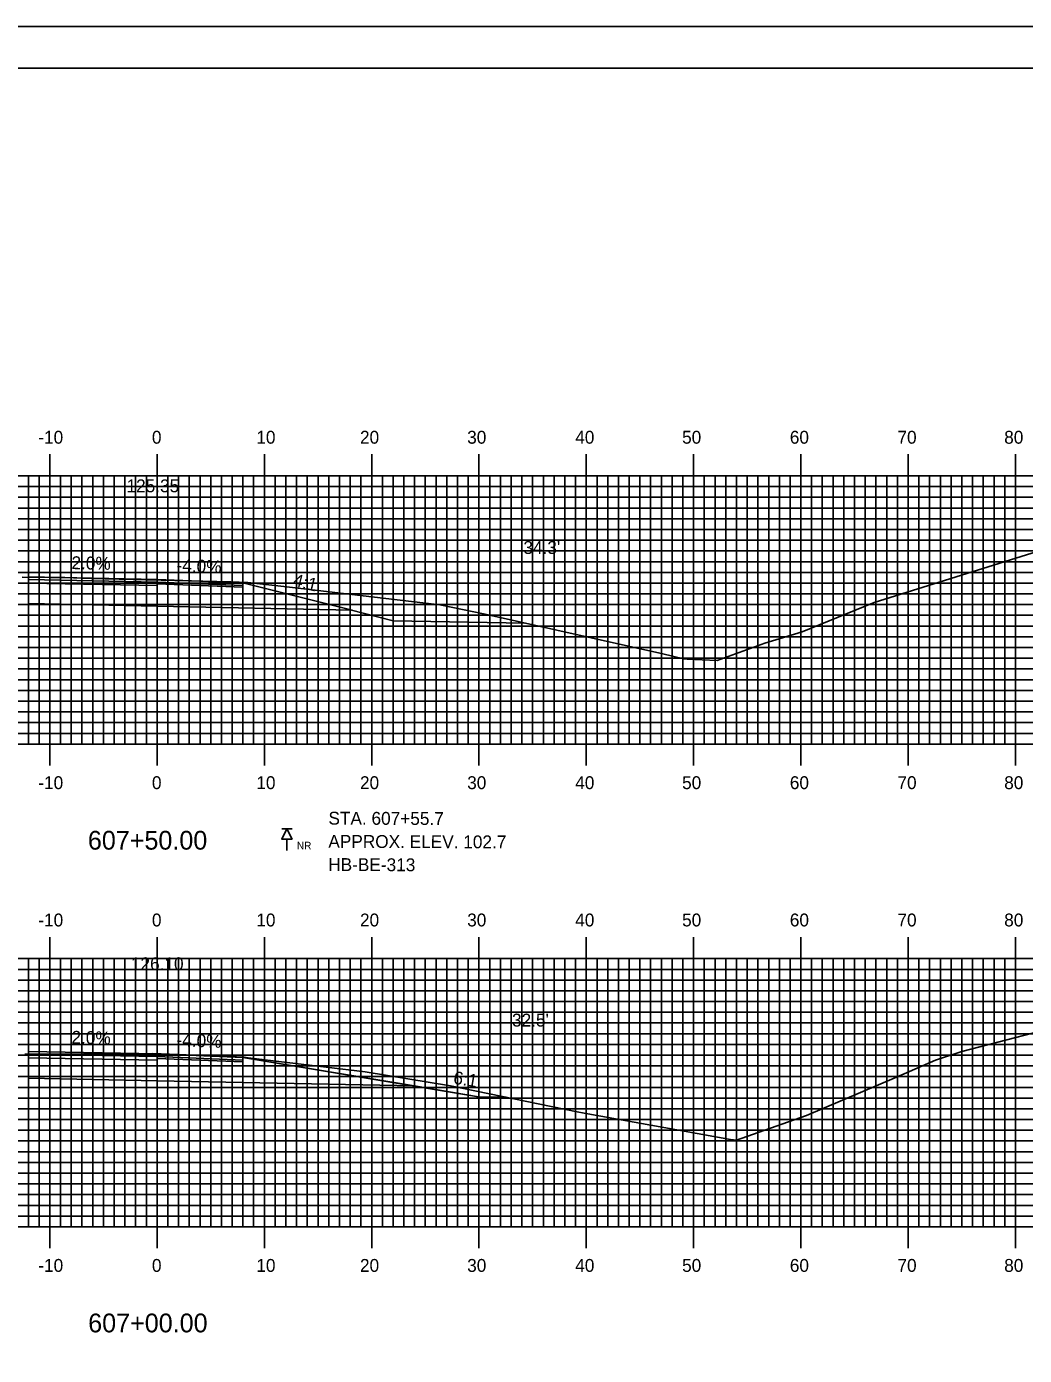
# Model space of a CAD drawing. Extents: x 842569 to 842912, y 363538 to 363758.
# Drawn here: x 842722.2 to 842815.2, y 363633.7 to 363757.6 of the extents above; entities that cross this region are included whole.
import ezdxf

# ---------------------------------------------------------------- set-up
doc = ezdxf.new("R2010")
doc.units = 0
for name, color, linetype in [('ANNOTATION', 7, 'Continuous'), ('BORDER', 7, 'Continuous'), ('BORING - NO REFUSAL', 7, 'Continuous'), ('D_Roadway_Centerline', 7, 'Continuous'), ('D_Roadway_Centerline_Text', 7, 'Continuous'), ('D_Roadway_Edge_Shoulder', 7, 'Continuous'), ('D_Roadway_Edge_TW', 7, 'Continuous'), ('D_Roadway_FinishedGrade', 7, 'Continuous'), ('D_Roadway_Pavement', 7, 'Continuous'), ('D_Roadway_SlopeLines', 7, 'Continuous'), ('D_Roadway_SubGrade', 7, 'Continuous'), ('D_Text_Standard', 7, 'Continuous'), ('H_V ANNOTATION', 7, 'Continuous'), ('MAJOR', 7, 'Continuous'), ('MINOR', 7, 'Continuous'), ('PLOT BOUNDARY', 7, 'Continuous'), ('S_Roadway_Centerline', 7, 'Continuous')]:
    doc.layers.add(name, color=color, linetype=linetype)

msp = doc.modelspace()

# ---------------------------------------------------------------- linework, layer by layer
at = {"layer": 'BORDER'}
msp.add_lwpolyline([(842584.8, 363543.72), (842904.8, 363543.72), (842904.8, 363753.72), (842584.8, 363753.72)], close=True, dxfattribs=at)
at = {"layer": 'BORING - NO REFUSAL'}
for p, q in [((842746.98, 363682.82), (842746.02, 363682.82)), ((842746.5, 363681.86), (842746.5, 363680.8))]:
    msp.add_line(p, q, dxfattribs=at)
msp.add_lwpolyline([(842746.5, 363682.82), (842746.98, 363681.86), (842746.02, 363681.86)], close=True, dxfattribs=at)
at = {"layer": 'D_Roadway_Centerline'}
for points in [[(842722.4, 363706.31), (842734.4, 363706.07), (842742.4, 363705.75), (842752.57, 363703.21)], [(842722.4, 363662.07), (842734.4, 363661.83), (842742.4, 363661.51), (842758.35, 363658.85), (842764.35, 363657.85)]]:
    msp.add_lwpolyline(points, dxfattribs=at)
at = {"layer": 'D_Roadway_Edge_Shoulder'}
msp.add_line((842722.4, 363706.06), (842722.4, 363706.31), dxfattribs=at)
for points in [[(842734.4, 363706.07), (842742.4, 363705.75), (842742.4, 363705.5), (842734.4, 363705.82)], [(842734.4, 363661.83), (842742.4, 363661.51), (842742.4, 363661.26), (842734.4, 363661.58)]]:
    msp.add_lwpolyline(points, close=True, dxfattribs=at)
at = {"layer": 'D_Roadway_Edge_TW'}
for points in [[(842722.4, 363706.31), (842734.4, 363706.07), (842734.4, 363705.82), (842722.4, 363706.06)], [(842722.4, 363662.07), (842734.4, 363661.83), (842734.4, 363661.58), (842722.4, 363661.82)]]:
    msp.add_lwpolyline(points, close=True, dxfattribs=at)
msp.add_lwpolyline([(842722.4, 363662.07), (842722.4, 363661.82)], dxfattribs=at)
at = {"layer": 'D_Roadway_FinishedGrade'}
for points in [[(842752.4, 363703.22), (842756.4, 363702.22), (842768.66, 363701.98)], [(842758.35, 363658.85), (842764.35, 363657.85), (842766.94, 363657.79)]]:
    msp.add_lwpolyline(points, dxfattribs=at)
at = {"layer": 'D_Roadway_Pavement'}
msp.add_line((842722.4, 363705.73), (842722.4, 363706.06), dxfattribs=at)
for points in [[(842722.4, 363706.06), (842734.4, 363705.82), (842734.4, 363705.49), (842722.4, 363705.73)], [(842734.4, 363705.82), (842742.4, 363705.5), (842742.4, 363705.34), (842734.4, 363705.66)], [(842722.4, 363661.82), (842734.4, 363661.58), (842734.4, 363661.24), (842722.4, 363661.48)], [(842734.4, 363661.58), (842742.4, 363661.26), (842742.4, 363661.09), (842734.4, 363661.41)]]:
    msp.add_lwpolyline(points, close=True, dxfattribs=at)
for points in [[(842734.4, 363705.82), (842734.4, 363705.49)], [(842734.4, 363705.82), (842734.4, 363705.49)], [(842722.4, 363661.82), (842722.4, 363661.48)], [(842734.4, 363661.58), (842734.4, 363661.24)], [(842734.4, 363661.58), (842734.4, 363661.24)]]:
    msp.add_lwpolyline(points, dxfattribs=at)
at = {"layer": 'D_Roadway_SlopeLines'}
msp.add_lwpolyline([(842742.4, 363661.51), (842764.35, 363657.85)], dxfattribs=at)
at = {"layer": 'D_Roadway_SubGrade'}
for p, q in [((842722.4, 363714.91), (842722.4, 363703.81)), ((842722.4, 363703.81), (842722.4, 363705.73)), ((842722.4, 363670.66), (842722.4, 363659.57))]:
    msp.add_line(p, q, dxfattribs=at)
for points in [[(842722.4, 363705.73), (842734.4, 363705.49), (842734.4, 363703.57), (842722.4, 363703.81)], [(842734.4, 363705.49), (842734.4, 363705.82), (842742.4, 363705.5), (842742.4, 363705.75), (842752.57, 363703.21), (842734.4, 363703.57)], [(842722.4, 363661.48), (842734.4, 363661.24), (842734.4, 363659.33), (842722.4, 363659.57)], [(842734.4, 363661.24), (842734.4, 363661.58), (842742.4, 363661.26), (842742.4, 363661.51), (842758.35, 363658.85), (842734.4, 363659.33)]]:
    msp.add_lwpolyline(points, close=True, dxfattribs=at)
msp.add_lwpolyline([(842722.4, 363661.48), (842722.4, 363659.57)], dxfattribs=at)
at = {"layer": 'MAJOR'}
for p, q in [((842724.4, 363717.73), (842724.4, 363715.72)), ((842734.4, 363717.73), (842734.4, 363715.72)), ((842744.4, 363717.73), (842744.4, 363715.72)), ((842754.4, 363717.73), (842754.4, 363715.72)), ((842764.4, 363717.73), (842764.4, 363715.72)), ((842774.4, 363717.73), (842774.4, 363715.72)), ((842784.4, 363717.73), (842784.4, 363715.72)), ((842794.4, 363717.73), (842794.4, 363715.72)), ((842804.4, 363717.73), (842804.4, 363715.72)), ((842814.4, 363717.73), (842814.4, 363715.72)), ((842594.4, 363715.72), (842874.4, 363715.72)), ((842594.4, 363715.72), (842874.4, 363715.72)), ((842724.4, 363690.72), (842724.4, 363715.72)), ((842734.4, 363690.72), (842734.4, 363715.72)), ((842744.4, 363690.72), (842744.4, 363715.72)), ((842754.4, 363690.72), (842754.4, 363715.72)), ((842764.4, 363690.72), (842764.4, 363715.72)), ((842774.4, 363690.72), (842774.4, 363715.72)), ((842784.4, 363690.72), (842784.4, 363715.72)), ((842794.4, 363690.72), (842794.4, 363715.72)), ((842804.4, 363690.72), (842804.4, 363715.72)), ((842814.4, 363690.72), (842814.4, 363715.72)), ((842594.4, 363710.72), (842874.4, 363710.72)), ((842594.4, 363705.72), (842874.4, 363705.72)), ((842594.4, 363700.72), (842874.4, 363700.72)), ((842594.4, 363695.72), (842874.4, 363695.72)), ((842594.4, 363690.72), (842874.4, 363690.72)), ((842594.4, 363690.72), (842874.4, 363690.72)), ((842724.4, 363688.72), (842724.4, 363690.72)), ((842734.4, 363688.72), (842734.4, 363690.72)), ((842744.4, 363688.72), (842744.4, 363690.72)), ((842754.4, 363688.72), (842754.4, 363690.72)), ((842764.4, 363688.72), (842764.4, 363690.72)), ((842774.4, 363688.72), (842774.4, 363690.72)), ((842784.4, 363688.72), (842784.4, 363690.72)), ((842794.4, 363688.72), (842794.4, 363690.72)), ((842804.4, 363688.72), (842804.4, 363690.72)), ((842814.4, 363688.72), (842814.4, 363690.72)), ((842724.4, 363672.73), (842724.4, 363670.72)), ((842734.4, 363672.73), (842734.4, 363670.72)), ((842744.4, 363672.73), (842744.4, 363670.72)), ((842754.4, 363672.73), (842754.4, 363670.72)), ((842764.4, 363672.73), (842764.4, 363670.72)), ((842774.4, 363672.73), (842774.4, 363670.72)), ((842784.4, 363672.73), (842784.4, 363670.72)), ((842794.4, 363672.73), (842794.4, 363670.72)), ((842804.4, 363672.73), (842804.4, 363670.72)), ((842814.4, 363672.73), (842814.4, 363670.72)), ((842594.4, 363670.72), (842874.4, 363670.72)), ((842594.4, 363670.72), (842874.4, 363670.72)), ((842724.4, 363645.72), (842724.4, 363670.72)), ((842734.4, 363645.72), (842734.4, 363670.72)), ((842744.4, 363645.72), (842744.4, 363670.72)), ((842754.4, 363645.72), (842754.4, 363670.72)), ((842764.4, 363645.72), (842764.4, 363670.72)), ((842774.4, 363645.72), (842774.4, 363670.72)), ((842784.4, 363645.72), (842784.4, 363670.72)), ((842794.4, 363645.72), (842794.4, 363670.72)), ((842804.4, 363645.72), (842804.4, 363670.72)), ((842814.4, 363645.72), (842814.4, 363670.72)), ((842594.4, 363665.72), (842874.4, 363665.72)), ((842594.4, 363660.72), (842874.4, 363660.72)), ((842594.4, 363655.72), (842874.4, 363655.72)), ((842594.4, 363650.72), (842874.4, 363650.72)), ((842594.4, 363645.72), (842874.4, 363645.72)), ((842594.4, 363645.72), (842874.4, 363645.72)), ((842724.4, 363643.72), (842724.4, 363645.72)), ((842734.4, 363643.72), (842734.4, 363645.72)), ((842744.4, 363643.72), (842744.4, 363645.72)), ((842754.4, 363643.72), (842754.4, 363645.72)), ((842764.4, 363643.72), (842764.4, 363645.72)), ((842774.4, 363643.72), (842774.4, 363645.72)), ((842784.4, 363643.72), (842784.4, 363645.72)), ((842794.4, 363643.72), (842794.4, 363645.72)), ((842804.4, 363643.72), (842804.4, 363645.72)), ((842814.4, 363643.72), (842814.4, 363645.72))]:
    msp.add_line(p, q, dxfattribs=at)
at = {"layer": 'MINOR'}
for p, q in [((842722.4, 363690.72), (842722.4, 363715.72)), ((842723.4, 363690.72), (842723.4, 363715.72)), ((842725.4, 363690.72), (842725.4, 363715.72)), ((842726.4, 363690.72), (842726.4, 363715.72)), ((842727.4, 363690.72), (842727.4, 363715.72)), ((842728.4, 363690.72), (842728.4, 363715.72)), ((842729.4, 363690.72), (842729.4, 363715.72)), ((842730.4, 363690.72), (842730.4, 363715.72)), ((842731.4, 363690.72), (842731.4, 363715.72)), ((842732.4, 363690.72), (842732.4, 363715.72)), ((842733.4, 363690.72), (842733.4, 363715.72)), ((842735.4, 363690.72), (842735.4, 363715.72)), ((842736.4, 363690.72), (842736.4, 363715.72)), ((842737.4, 363690.72), (842737.4, 363715.72)), ((842738.4, 363690.72), (842738.4, 363715.72)), ((842739.4, 363690.72), (842739.4, 363715.72)), ((842740.4, 363690.72), (842740.4, 363715.72)), ((842741.4, 363690.72), (842741.4, 363715.72)), ((842742.4, 363690.72), (842742.4, 363715.72)), ((842743.4, 363690.72), (842743.4, 363715.72)), ((842745.4, 363690.72), (842745.4, 363715.72)), ((842746.4, 363690.72), (842746.4, 363715.72)), ((842747.4, 363690.72), (842747.4, 363715.72)), ((842748.4, 363690.72), (842748.4, 363715.72)), ((842749.4, 363690.72), (842749.4, 363715.72)), ((842750.4, 363690.72), (842750.4, 363715.72)), ((842751.4, 363690.72), (842751.4, 363715.72)), ((842752.4, 363690.72), (842752.4, 363715.72)), ((842753.4, 363690.72), (842753.4, 363715.72)), ((842755.4, 363690.72), (842755.4, 363715.72)), ((842756.4, 363690.72), (842756.4, 363715.72)), ((842757.4, 363690.72), (842757.4, 363715.72)), ((842758.4, 363690.72), (842758.4, 363715.72)), ((842759.4, 363690.72), (842759.4, 363715.72)), ((842760.4, 363690.72), (842760.4, 363715.72)), ((842761.4, 363690.72), (842761.4, 363715.72)), ((842762.4, 363690.72), (842762.4, 363715.72)), ((842763.4, 363690.72), (842763.4, 363715.72)), ((842765.4, 363690.72), (842765.4, 363715.72)), ((842766.4, 363690.72), (842766.4, 363715.72)), ((842767.4, 363690.72), (842767.4, 363715.72)), ((842768.4, 363690.72), (842768.4, 363715.72)), ((842769.4, 363690.72), (842769.4, 363715.72)), ((842770.4, 363690.72), (842770.4, 363715.72)), ((842771.4, 363690.72), (842771.4, 363715.72)), ((842772.4, 363690.72), (842772.4, 363715.72)), ((842773.4, 363690.72), (842773.4, 363715.72)), ((842775.4, 363690.72), (842775.4, 363715.72)), ((842776.4, 363690.72), (842776.4, 363715.72)), ((842777.4, 363690.72), (842777.4, 363715.72)), ((842778.4, 363690.72), (842778.4, 363715.72)), ((842779.4, 363690.72), (842779.4, 363715.72)), ((842780.4, 363690.72), (842780.4, 363715.72)), ((842781.4, 363690.72), (842781.4, 363715.72)), ((842782.4, 363690.72), (842782.4, 363715.72)), ((842783.4, 363690.72), (842783.4, 363715.72)), ((842785.4, 363690.72), (842785.4, 363715.72)), ((842786.4, 363690.72), (842786.4, 363715.72)), ((842787.4, 363690.72), (842787.4, 363715.72)), ((842788.4, 363690.72), (842788.4, 363715.72)), ((842789.4, 363690.72), (842789.4, 363715.72)), ((842790.4, 363690.72), (842790.4, 363715.72)), ((842791.4, 363690.72), (842791.4, 363715.72)), ((842792.4, 363690.72), (842792.4, 363715.72)), ((842793.4, 363690.72), (842793.4, 363715.72)), ((842795.4, 363690.72), (842795.4, 363715.72)), ((842796.4, 363690.72), (842796.4, 363715.72)), ((842797.4, 363690.72), (842797.4, 363715.72)), ((842798.4, 363690.72), (842798.4, 363715.72)), ((842799.4, 363690.72), (842799.4, 363715.72)), ((842800.4, 363690.72), (842800.4, 363715.72)), ((842801.4, 363690.72), (842801.4, 363715.72)), ((842802.4, 363690.72), (842802.4, 363715.72)), ((842803.4, 363690.72), (842803.4, 363715.72)), ((842805.4, 363690.72), (842805.4, 363715.72)), ((842806.4, 363690.72), (842806.4, 363715.72)), ((842807.4, 363690.72), (842807.4, 363715.72)), ((842808.4, 363690.72), (842808.4, 363715.72)), ((842809.4, 363690.72), (842809.4, 363715.72)), ((842810.4, 363690.72), (842810.4, 363715.72)), ((842811.4, 363690.72), (842811.4, 363715.72)), ((842812.4, 363690.72), (842812.4, 363715.72)), ((842813.4, 363690.72), (842813.4, 363715.72)), ((842594.4, 363714.72), (842874.4, 363714.72)), ((842594.4, 363713.72), (842874.4, 363713.72)), ((842594.4, 363712.72), (842874.4, 363712.72)), ((842594.4, 363711.72), (842874.4, 363711.72)), ((842594.4, 363709.72), (842874.4, 363709.72)), ((842594.4, 363708.72), (842874.4, 363708.72)), ((842594.4, 363707.72), (842874.4, 363707.72)), ((842594.4, 363706.72), (842874.4, 363706.72)), ((842594.4, 363704.72), (842874.4, 363704.72)), ((842594.4, 363703.72), (842874.4, 363703.72)), ((842594.4, 363702.72), (842874.4, 363702.72)), ((842594.4, 363701.72), (842874.4, 363701.72)), ((842594.4, 363699.72), (842874.4, 363699.72)), ((842594.4, 363698.72), (842874.4, 363698.72)), ((842594.4, 363697.72), (842874.4, 363697.72)), ((842594.4, 363696.72), (842874.4, 363696.72)), ((842594.4, 363694.72), (842874.4, 363694.72)), ((842594.4, 363693.72), (842874.4, 363693.72)), ((842594.4, 363692.72), (842874.4, 363692.72)), ((842594.4, 363691.72), (842874.4, 363691.72)), ((842594.4, 363669.72), (842874.4, 363669.72)), ((842722.4, 363645.72), (842722.4, 363670.72)), ((842723.4, 363645.72), (842723.4, 363670.72)), ((842725.4, 363645.72), (842725.4, 363670.72)), ((842726.4, 363645.72), (842726.4, 363670.72)), ((842727.4, 363645.72), (842727.4, 363670.72)), ((842728.4, 363645.72), (842728.4, 363670.72)), ((842729.4, 363645.72), (842729.4, 363670.72)), ((842730.4, 363645.72), (842730.4, 363670.72)), ((842731.4, 363645.72), (842731.4, 363670.72)), ((842732.4, 363645.72), (842732.4, 363670.72)), ((842733.4, 363645.72), (842733.4, 363670.72)), ((842735.4, 363645.72), (842735.4, 363670.72)), ((842736.4, 363645.72), (842736.4, 363670.72)), ((842737.4, 363645.72), (842737.4, 363670.72)), ((842738.4, 363645.72), (842738.4, 363670.72)), ((842739.4, 363645.72), (842739.4, 363670.72)), ((842740.4, 363645.72), (842740.4, 363670.72)), ((842741.4, 363645.72), (842741.4, 363670.72)), ((842742.4, 363645.72), (842742.4, 363670.72)), ((842743.4, 363645.72), (842743.4, 363670.72)), ((842745.4, 363645.72), (842745.4, 363670.72)), ((842746.4, 363645.72), (842746.4, 363670.72)), ((842747.4, 363645.72), (842747.4, 363670.72)), ((842748.4, 363645.72), (842748.4, 363670.72)), ((842749.4, 363645.72), (842749.4, 363670.72)), ((842750.4, 363645.72), (842750.4, 363670.72)), ((842751.4, 363645.72), (842751.4, 363670.72)), ((842752.4, 363645.72), (842752.4, 363670.72)), ((842753.4, 363645.72), (842753.4, 363670.72)), ((842755.4, 363645.72), (842755.4, 363670.72)), ((842756.4, 363645.72), (842756.4, 363670.72)), ((842757.4, 363645.72), (842757.4, 363670.72)), ((842758.4, 363645.72), (842758.4, 363670.72)), ((842759.4, 363645.72), (842759.4, 363670.72)), ((842760.4, 363645.72), (842760.4, 363670.72)), ((842761.4, 363645.72), (842761.4, 363670.72)), ((842762.4, 363645.72), (842762.4, 363670.72)), ((842763.4, 363645.72), (842763.4, 363670.72)), ((842765.4, 363645.72), (842765.4, 363670.72)), ((842766.4, 363645.72), (842766.4, 363670.72)), ((842767.4, 363645.72), (842767.4, 363670.72)), ((842768.4, 363645.72), (842768.4, 363670.72)), ((842769.4, 363645.72), (842769.4, 363670.72)), ((842770.4, 363645.72), (842770.4, 363670.72)), ((842771.4, 363645.72), (842771.4, 363670.72)), ((842772.4, 363645.72), (842772.4, 363670.72)), ((842773.4, 363645.72), (842773.4, 363670.72)), ((842775.4, 363645.72), (842775.4, 363670.72)), ((842776.4, 363645.72), (842776.4, 363670.72)), ((842777.4, 363645.72), (842777.4, 363670.72)), ((842778.4, 363645.72), (842778.4, 363670.72)), ((842779.4, 363645.72), (842779.4, 363670.72)), ((842780.4, 363645.72), (842780.4, 363670.72)), ((842781.4, 363645.72), (842781.4, 363670.72)), ((842782.4, 363645.72), (842782.4, 363670.72)), ((842783.4, 363645.72), (842783.4, 363670.72)), ((842785.4, 363645.72), (842785.4, 363670.72)), ((842786.4, 363645.72), (842786.4, 363670.72)), ((842787.4, 363645.72), (842787.4, 363670.72)), ((842788.4, 363645.72), (842788.4, 363670.72)), ((842789.4, 363645.72), (842789.4, 363670.72)), ((842790.4, 363645.72), (842790.4, 363670.72)), ((842791.4, 363645.72), (842791.4, 363670.72)), ((842792.4, 363645.72), (842792.4, 363670.72)), ((842793.4, 363645.72), (842793.4, 363670.72)), ((842795.4, 363645.72), (842795.4, 363670.72)), ((842796.4, 363645.72), (842796.4, 363670.72)), ((842797.4, 363645.72), (842797.4, 363670.72)), ((842798.4, 363645.72), (842798.4, 363670.72)), ((842799.4, 363645.72), (842799.4, 363670.72)), ((842800.4, 363645.72), (842800.4, 363670.72)), ((842801.4, 363645.72), (842801.4, 363670.72)), ((842802.4, 363645.72), (842802.4, 363670.72)), ((842803.4, 363645.72), (842803.4, 363670.72)), ((842805.4, 363645.72), (842805.4, 363670.72)), ((842806.4, 363645.72), (842806.4, 363670.72)), ((842807.4, 363645.72), (842807.4, 363670.72)), ((842808.4, 363645.72), (842808.4, 363670.72)), ((842809.4, 363645.72), (842809.4, 363670.72)), ((842810.4, 363645.72), (842810.4, 363670.72)), ((842811.4, 363645.72), (842811.4, 363670.72)), ((842812.4, 363645.72), (842812.4, 363670.72)), ((842813.4, 363645.72), (842813.4, 363670.72)), ((842594.4, 363668.72), (842874.4, 363668.72)), ((842594.4, 363667.72), (842874.4, 363667.72)), ((842594.4, 363666.72), (842874.4, 363666.72)), ((842594.4, 363664.72), (842874.4, 363664.72)), ((842594.4, 363663.72), (842874.4, 363663.72)), ((842594.4, 363662.72), (842874.4, 363662.72)), ((842594.4, 363661.72), (842874.4, 363661.72)), ((842594.4, 363659.72), (842874.4, 363659.72)), ((842594.4, 363658.72), (842874.4, 363658.72)), ((842594.4, 363657.72), (842874.4, 363657.72)), ((842594.4, 363656.72), (842874.4, 363656.72)), ((842594.4, 363654.72), (842874.4, 363654.72)), ((842594.4, 363653.72), (842874.4, 363653.72)), ((842594.4, 363652.72), (842874.4, 363652.72)), ((842594.4, 363651.72), (842874.4, 363651.72)), ((842594.4, 363649.72), (842874.4, 363649.72)), ((842594.4, 363648.72), (842874.4, 363648.72)), ((842594.4, 363647.72), (842874.4, 363647.72)), ((842594.4, 363646.72), (842874.4, 363646.72))]:
    msp.add_line(p, q, dxfattribs=at)
at = {"layer": 'PLOT BOUNDARY'}
msp.add_lwpolyline([(842568.61, 363537.6), (842908.61, 363537.6), (842908.61, 363757.6), (842568.61, 363757.6)], close=True, dxfattribs=at)
at = {"layer": 'S_Roadway_Centerline'}
for points in [[(842721.84, 363706.28), (842724.47, 363706.26), (842725.81, 363706.25), (842728.27, 363706.16), (842741.26, 363705.85), (842742.86, 363705.78), (842746.49, 363705.39), (842754.14, 363704.48), (842760.75, 363703.69), (842764.97, 363702.83), (842781.54, 363699.12), (842783.46, 363698.68), (842783.8, 363698.63), (842786.61, 363698.5), (842791.05, 363700.12), (842794.52, 363701.19), (842801.24, 363703.93), (842819.99, 363709.79)], [(842722.07, 363661.8), (842732.91, 363661.84), (842734.01, 363661.86), (842741.79, 363661.55), (842742.32, 363661.54), (842742.33, 363661.55), (842742.9, 363661.48), (842753.8, 363660.16), (842761.74, 363658.86), (842773.54, 363656.44), (842774.19, 363656.32), (842787.85, 363653.87), (842788.4, 363653.81), (842789.9, 363654.33), (842794.92, 363656.08), (842803.32, 363659.68), (842806.96, 363661.25), (842809.41, 363662.06), (842820.19, 363664.87)]]:
    msp.add_lwpolyline(points, dxfattribs=at)

# ---------------------------------------------------------------- texts
at = {"layer": 'ANNOTATION'}
for s, rotation, p in [('2.0%', 358.8542, (842726.41, 363707.03)), ('-4.0%', 357.7094, (842736.19, 363706.8)), ('4:1', 345.9638, (842746.99, 363705.47)), ('2.0%', 358.8542, (842726.41, 363662.79)), ('-4.0%', 357.7094, (842736.19, 363662.56)), ('6:1', 350.5375, (842761.95, 363659.07))]:
    msp.add_text(s, height=1.2, rotation=rotation, dxfattribs=at).set_placement(p)
at = {"layer": 'BORING - NO REFUSAL'}
for s, p in [('STA. 607+55.7', (842750.37, 363683.21)), ('APPROX. ELEV. 102.7', (842750.36, 363681.05)), ('HB-BE-313', (842750.35, 363678.89))]:
    msp.add_text(s, height=1.2, rotation=359.8142, dxfattribs=at).set_placement(p)
msp.add_text('NR', height=0.7, dxfattribs=at).set_placement((842747.43, 363680.91))
at = {"layer": 'D_Roadway_Centerline_Text'}
for s, p in [('125.35', (842731.55, 363714.19)), ('126.10', (842731.96, 363669.64))]:
    msp.add_text(s, height=1.2, dxfattribs=at).set_placement(p)
at = {"layer": 'D_Text_Standard'}
for s, p in [("34.3'", (842768.54, 363708.44)), ("32.5'", (842767.48, 363664.39))]:
    msp.add_text(s, height=1.2, dxfattribs=at).set_placement(p)
at = {"layer": 'H_V ANNOTATION'}
for s, height, p in [('-10', 1.2, (842723.33, 363718.72)), ('0', 1.2, (842733.92, 363718.72)), ('10', 1.2, (842743.65, 363718.72)), ('20', 1.2, (842753.31, 363718.72)), ('30', 1.2, (842763.3, 363718.72)), ('40', 1.2, (842773.37, 363718.72)), ('50', 1.2, (842783.33, 363718.72)), ('60', 1.2, (842793.37, 363718.72)), ('70', 1.2, (842803.4, 363718.72)), ('80', 1.2, (842813.35, 363718.72)), ('-10', 1.2, (842723.33, 363686.52)), ('0', 1.2, (842733.92, 363686.52)), ('10', 1.2, (842743.65, 363686.52)), ('20', 1.2, (842753.31, 363686.52)), ('30', 1.2, (842763.3, 363686.52)), ('40', 1.2, (842773.37, 363686.52)), ('50', 1.2, (842783.33, 363686.52)), ('60', 1.2, (842793.37, 363686.52)), ('70', 1.2, (842803.4, 363686.52)), ('80', 1.2, (842813.35, 363686.52)), ('607+50.00', 1.75, (842727.95, 363680.88)), ('-10', 1.2, (842723.33, 363673.72)), ('0', 1.2, (842733.92, 363673.72)), ('10', 1.2, (842743.65, 363673.72)), ('20', 1.2, (842753.31, 363673.72)), ('30', 1.2, (842763.3, 363673.72)), ('40', 1.2, (842773.37, 363673.72)), ('50', 1.2, (842783.33, 363673.72)), ('60', 1.2, (842793.37, 363673.72)), ('70', 1.2, (842803.4, 363673.72)), ('80', 1.2, (842813.35, 363673.72)), ('-10', 1.2, (842723.33, 363641.52)), ('0', 1.2, (842733.92, 363641.52)), ('10', 1.2, (842743.65, 363641.52)), ('20', 1.2, (842753.31, 363641.52)), ('30', 1.2, (842763.3, 363641.52)), ('40', 1.2, (842773.37, 363641.52)), ('50', 1.2, (842783.33, 363641.52)), ('60', 1.2, (842793.37, 363641.52)), ('70', 1.2, (842803.4, 363641.52)), ('80', 1.2, (842813.35, 363641.52)), ('607+00.00', 1.75, (842727.98, 363635.88))]:
    msp.add_text(s, height=height, dxfattribs=at).set_placement(p)

doc.saveas('drawing.dxf')
